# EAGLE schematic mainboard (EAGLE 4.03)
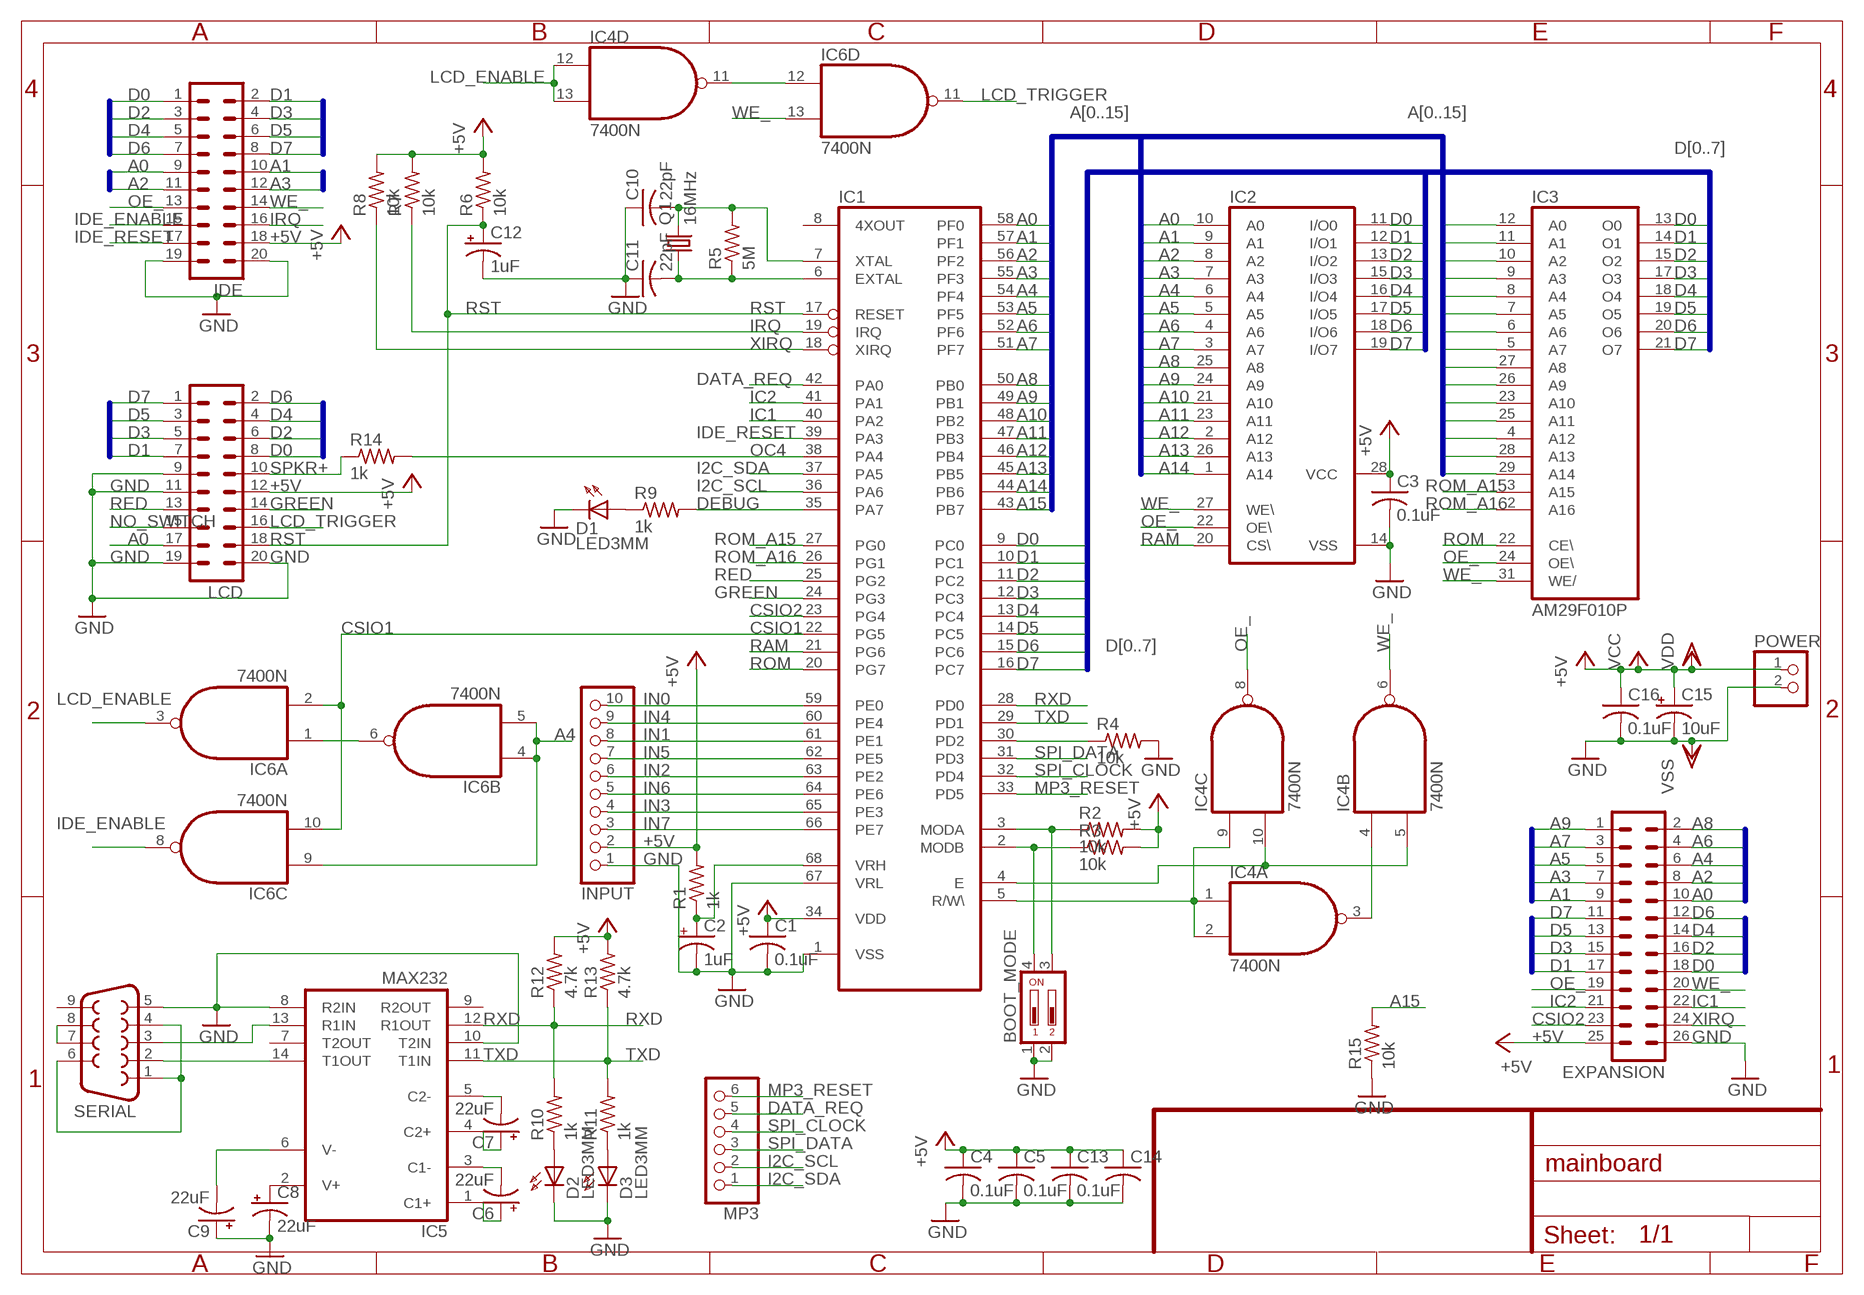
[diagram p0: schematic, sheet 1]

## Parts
BOOT_MODE  DIP02YL  [DIP02YL]
C1  0.1uF  C-US050-025X075  [C050-025X075]
C2  1uF  CPOL-USTAP5-60  [TAP5-60]
C3  0.1uF  C-US050-025X075  [C050-025X075]
C4  0.1uF  C-US050-025X075  [C050-025X075]
C5  0.1uF  C-US050-025X075  [C050-025X075]
C6  22uF  CPOL-USTAP5-60  [TAP5-60]
C7  22uF  CPOL-USTAP5-60  [TAP5-60]
C8  22uF  CPOL-USTAP5-60  [TAP5-60]
C9  22uF  CPOL-USTAP5-60  [TAP5-60]
C10  22pF  C-US050-025X075  [C050-025X075]
C11  22pF  C-US050-025X075  [C050-025X075]
C12  1uF  CPOL-USTAP5-60  [TAP5-60]
C13  0.1uF  C-US050-025X075  [C050-025X075]
C14  C-US050-025X075  [C050-025X075]
C15  10uF  CPOL-USTAP5-60  [TAP5-60]
C16  0.1uF  C-US050-025X075  [C050-025X075]
D1  LED3MM  [LED3MM]
D2  LED3MM  [LED3MM]
D3  LED3MM  [LED3MM]
EXPANSION  26V  [26V]
IC1  68HC11F1-S  [PLCC-68]
IC2  62256P  [DIL28-6]
IC3  AM29F010P  [DIL32-3]
IC4  7400N  [DIL14]
IC5  MAX232  [DIL16]
IC6  7400N  [DIL14]
IDE  20V  [20V]
INPUT  PINHD-1X10  [1X10]
LCD  20V  [20V]
MP3  PINHD-1X6  [1X06]
POWER  PINHD-1X2  [1X02]
Q1  16MHz  HC49U-V  [HC49U-V]
R1  1k  R-US_0207/10  [0207/10]
R2  10k  R-US_0207/10  [0207/10]
R3  10k  R-US_0207/10  [0207/10]
R4  10k  R-US_0207/10  [0207/10]
R5  5M  R-US_0207/10  [0207/10]
R6  10k  R-US_0207/10  [0207/10]
R7  10k  R-US_0207/10  [0207/10]
R8  10k  R-US_0207/10  [0207/10]
R9  1k  R-US_0207/10  [0207/10]
R10  1k  R-US_0207/10  [0207/10]
R11  1k  R-US_0207/10  [0207/10]
R12  4.7k  R-US_0207/10  [0207/10]
R13  4.7k  R-US_0207/10  [0207/10]
R14  1k  R-US_0207/10  [0207/10]
R15  10k  R-US_0207/10  [0207/10]
SERIAL  F09H  [F09H]

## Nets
+5V: C1.1 C3.1 C4.1 C5.1 C13.1 C14.1 EXPANSION.25 IC1.34(VDD) IC2.28(VCC) IDE.18 INPUT.2 LCD.12 R1.2 R2.2 R3.2 R6.2 R7.2 R8.2 R12.2 R13.2
A0: EXPANSION.10 IC1.58(PF0) IC2.10(A0) IC3.12(A0) IDE.9 LCD.17
A1: EXPANSION.9 IC1.57(PF1) IC2.9(A1) IC3.11(A1) IDE.10
A2: EXPANSION.8 IC1.56(PF2) IC2.8(A2) IC3.10(A2) IDE.11
A3: EXPANSION.7 IC1.55(PF3) IC2.7(A3) IC3.9(A3) IDE.12
A4: EXPANSION.6 IC1.54(PF4) IC2.6(A4) IC3.8(A4) IC6.4(B:I0) IC6.5(B:I1) IC6.9(C:I0)
A5: EXPANSION.5 IC1.53(PF5) IC2.5(A5) IC3.7(A5)
A6: EXPANSION.4 IC1.52(PF6) IC2.4(A6) IC3.6(A6)
A7: EXPANSION.3 IC1.51(PF7) IC2.3(A7) IC3.5(A7)
A8: EXPANSION.2 IC1.50(PB0) IC2.25(A8) IC3.27(A8)
A9: EXPANSION.1 IC1.49(PB1) IC2.24(A9) IC3.26(A9)
A10: IC1.48(PB2) IC2.21(A10) IC3.23(A10)
A11: IC1.47(PB3) IC2.23(A11) IC3.25(A11)
A12: IC1.46(PB4) IC2.2(A12) IC3.4(A12)
A13: IC1.45(PB5) IC2.26(A13) IC3.28(A13)
A14: IC1.44(PB6) IC2.1(A14) IC3.29(A14)
A15: IC1.43(PB7) R15.2
CSIO1: IC1.22(PG5) IC6.2(A:I1) IC6.10(C:I1)
CSIO2: EXPANSION.23 IC1.23(PG4)
D0: EXPANSION.18 IC1.9(PC0) IC2.11(I/O0) IC3.13(O0) IDE.1 LCD.8
D1: EXPANSION.17 IC1.10(PC1) IC2.12(I/O1) IC3.14(O1) IDE.2 LCD.7
D2: EXPANSION.16 IC1.11(PC2) IC2.13(I/O2) IC3.15(O2) IDE.3 LCD.6
D3: EXPANSION.15 IC1.12(PC3) IC2.15(I/O3) IC3.17(O3) IDE.4 LCD.5
D4: EXPANSION.14 IC1.13(PC4) IC2.16(I/O4) IC3.18(O4) IDE.5 LCD.4
D5: EXPANSION.13 IC1.14(PC5) IC2.17(I/O5) IC3.19(O5) IDE.6 LCD.3
D6: EXPANSION.12 IC1.15(PC6) IC2.18(I/O6) IC3.20(O6) IDE.7 LCD.2
D7: EXPANSION.11 IC1.16(PC7) IC2.19(I/O7) IC3.21(O7) IDE.8 LCD.1
DATA_REQ: IC1.42(PA0) MP3.5
DEBUG: IC1.35(PA7) R9.2
GND: BOOT_MODE.1 BOOT_MODE.2 C1.2 C2.- C3.2 C4.2 C5.2 C8.- C9.+ C10.1 C11.1 C12.- C13.2 C14.2 D1.K(C) D2.K(C) D3.K(C) EXPANSION.26 IC1.1(VSS) IC1.67(VRL) IC2.14(VSS) IC5.8(R2IN) IC5.10(T2IN) IDE.19 IDE.20 INPUT.1 LCD.9 LCD.11 LCD.19 LCD.20 R4.2 R15.1 SERIAL.5
GREEN: IC1.24(PG3) LCD.14
I2C_SCL: IC1.36(PA6) MP3.2
I2C_SDA: IC1.37(PA5) MP3.1
IC1: EXPANSION.22 IC1.40(PA2)
IC2: EXPANSION.21 IC1.41(PA1)
IDE_ENABLE: IC6.8(C:O) IDE.15
IDE_RESET: IC1.39(PA3) IDE.17
IN0: IC1.59(PE0) INPUT.10
IN1: IC1.61(PE1) INPUT.8
IN2: IC1.63(PE2) INPUT.6
IN3: IC1.65(PE3) INPUT.4
IN4: IC1.60(PE4) INPUT.9
IN5: IC1.62(PE5) INPUT.7
IN6: IC1.64(PE6) INPUT.5
IN7: IC1.66(PE7) INPUT.3
IRQ: IC1.19(IRQ) IDE.16 R7.1
LCD_ENABLE: IC4.12(D:I0) IC4.13(D:I1) IC6.3(A:O)
LCD_TRIGGER: IC6.11(D:O) LCD.16
MP3_RESET: IC1.33(PD5) MP3.6
N$1: C2.+ IC1.68(VRH) R1.1
N$2: BOOT_MODE.4 IC1.2(MODB) R3.1
N$3: BOOT_MODE.3 IC1.3(MODA) R2.1
N$4: IC4.3(A:O) IC4.4(B:I0)
N$5: IC1.4(E) IC4.5(B:I1) IC4.10(C:I1)
N$6: IC1.5(R/W\) IC4.1(A:I0) IC4.2(A:I1) IC4.9(C:I0)
N$7: C7.- IC5.5(C2-)
N$8: C7.+ IC5.4(C2+)
N$9: C6.- IC5.3(C1-)
N$10: IC1.30(PD2) R4.1
N$11: C6.+ IC5.1(C1+)
N$12: C8.+ IC5.2(V+)
N$13: C9.- IC5.6(V-)
N$14: IC5.13(R1IN) SERIAL.3
N$15: IC5.14(T1OUT) SERIAL.2
N$16: SERIAL.1 SERIAL.4 SERIAL.6
N$17: SERIAL.7 SERIAL.8
N$18: C11.2 IC1.6(EXTAL) Q1.1 R5.1
N$19: C10.2 IC1.7(XTAL) Q1.2 R5.2
N$20: IC6.1(A:I0) IC6.6(B:O)
N$21: D1.A R9.1
N$22: D2.A R10.1
N$23: D3.A R11.1
N$25: IC4.11(D:O) IC6.12(D:I0)
NO_SWITCH: LCD.15
OC4: IC1.38(PA4) R14.2
OE_: EXPANSION.19 IC2.22(OE\) IC3.24(OE\) IC4.8(C:O) IDE.13
RAM: IC1.21(PG6) IC2.20(CS\)
RED: IC1.25(PG2) LCD.13
ROM: IC1.20(PG7) IC3.22(CE\)
ROM_A15: IC1.27(PG0) IC3.3(A15)
ROM_A16: IC1.26(PG1) IC3.2(A16)
RST: C12.+ IC1.17(RESET) LCD.18 R6.1
RXD: IC1.28(PD0) IC5.12(R1OUT) R10.2 R12.1
SPI_CLOCK: IC1.32(PD4) MP3.4
SPI_DATA: IC1.31(PD3) MP3.3
SPKR+: LCD.10 R14.1
TXD: IC1.29(PD1) IC5.11(T1IN) R11.2 R13.1
VDD: C15.+ C16.1 POWER.1 ; supply symbol labelled VCC, +5V
VSS: C15.- C16.2 POWER.2 ; supply symbol labelled GND
WE_: EXPANSION.20 IC2.27(WE\) IC3.31(WE/) IC4.6(B:O) IC6.13(D:I1) IDE.14
XIRQ: EXPANSION.24 IC1.18(XIRQ) R8.1
Unconnected: IC1.8(4XOUT) IC3.1(NC) IC3.30(NC) IC5.7(T2OUT) IC5.9(R2OUT) SERIAL.9

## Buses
A[0..15]
D[0..7]
A[0..3]
A[0..9]

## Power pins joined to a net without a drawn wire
GND: IC3.16(GND) IC4.7(P:GND) IC5.15(GND) IC6.7(P:GND)
VCC: IC3.32(VCC) IC4.14(P:VCC) IC5.16(VCC) IC6.14(P:VCC)

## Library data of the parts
BOOT_MODE = switch-dil:DIP02YL: DIL/CODE SWITCH
C1 C3-C5 C10 C11 C13 C14 C16 = rcl:C-US: CAPACITOR, American symbol
C2 C6-C9 C12 C15 = rcl:CPOL-US: POLARIZED CAPACITOR, American symbol
D1-D3 = led:LED3MM: LED
EXPANSION = con-harting-v:26V: CONNECTOR
IC1 = chris:68HC11F1-S: 68HC11 F1 Microcontroller
IC2 = memory-hitachi:62256P: MEMORY
IC3 = am29-memory:AM29F010*: 1-Megabit FLASH MEMORY (128 K x 8 bit) 5 V-only
IC4 IC6 = 74xx-us:74*00: Quad 2-input NAND gate
IC5 = maxim:MAX232: RS232 TRANSEIVER
IDE LCD = con-harting-v:20V: CONNECTOR
INPUT = pinhead:PINHD-1X10: PIN HEADER
MP3 = pinhead:PINHD-1X6: PIN HEADER
POWER = pinhead:PINHD-1X2: PIN HEADER
Q1 = crystal:HC49U-V: CRYSTAL
R1-R15 = rcl:R-US_: RESISTOR, American symbol
SERIAL = con-subd:F09H: HARTING SUB-D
